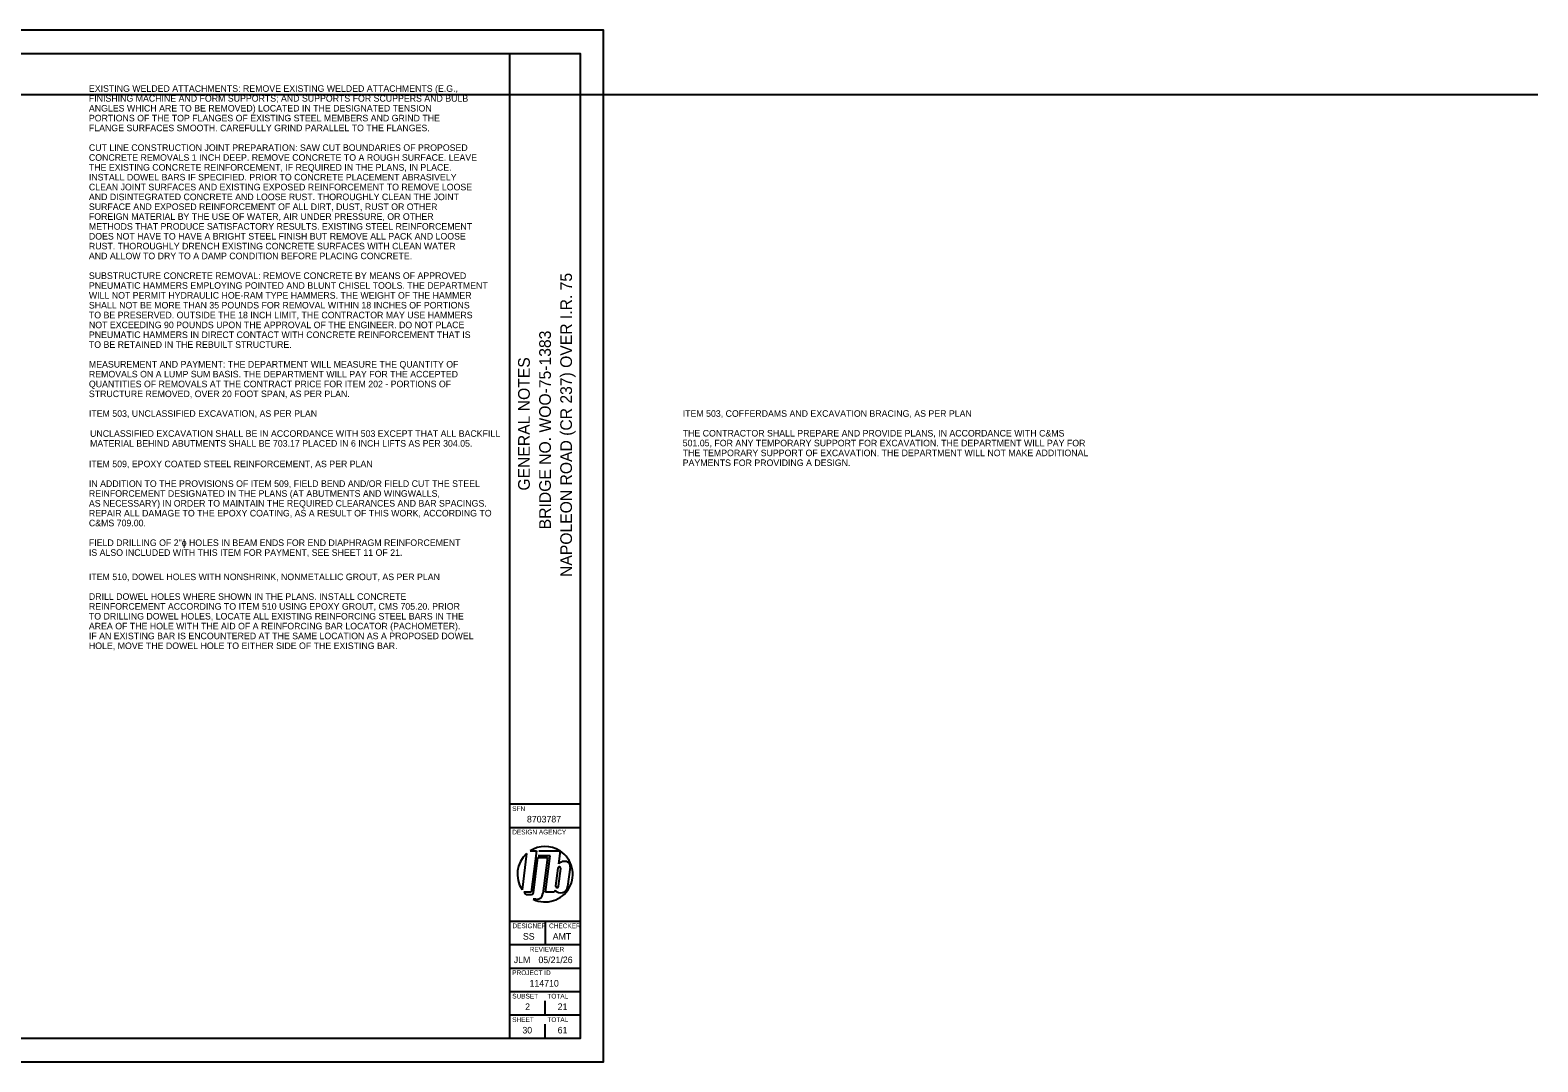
# Model space of a CAD drawing. Extents: x -11.1 to 53.9, y -2 to 22.
# Drawn here: x 21.76 to 53.93, y 0 to 22 of the extents above; entities that cross this region are included whole.
import ezdxf

# ---------------------------------------------------------------- set-up
doc = ezdxf.new("R2010")
doc.units = 0
for name, color, linetype in [('BR_P_Gen_Text', 7, 'Continuous'), ('SC_Scratch1', 7, 'Continuous'), ('SH_Border', 7, 'Continuous'), ('SH_Cut_Line', 7, 'Continuous'), ('SH_Data', 7, 'Continuous')]:
    doc.layers.add(name, color=color, linetype=linetype)

msp = doc.modelspace()

# ---------------------------------------------------------------- linework, layer by layer
at = {"layer": 'SC_Scratch1'}
msp.add_line((2.753, 20.628), (53.932, 20.628), dxfattribs=at)
at = {"layer": 'SH_Border'}
for p, q in [((32, 0.5), (32, 21.5)), ((32, 5.5), (33.5, 5.5)), ((32, 5), (33.5, 5)), ((32, 3), (33.5, 3)), ((32.75, 3), (32.75, 2.5)), ((32, 2.5), (33.5, 2.5)), ((32, 2), (33.5, 2)), ((32, 1.5), (33.5, 1.5)), ((32, 1), (33.5, 1))]:
    msp.add_line(p, q, dxfattribs=at)
msp.add_lwpolyline([(1.5, 21.5), (33.5, 21.5), (33.5, 0.5), (1.5, 0.5)], close=True, dxfattribs=at)
at = {"layer": 'SH_Cut_Line'}
msp.add_lwpolyline([(0, 0), (34, 0), (34, 22), (0, 22)], close=True, dxfattribs=at)
at = {"layer": 'SH_Data'}
for p, q in [((32.356, 4.44), (32.259, 3.671)), ((32.432, 4.498), (32.567, 4.498)), ((32.567, 4.498), (32.456, 3.618)), ((32.504, 3.604), (32.599, 4.355)), ((32.599, 4.355), (32.801, 4.355)), ((32.856, 4.396), (32.604, 4.396)), ((32.617, 4.5), (33.065, 4.5)), ((32.801, 4.355), (32.704, 3.589)), ((32.758, 3.618), (32.856, 4.396)), ((33.07, 4.496), (33.035, 4.22)), ((32.75, 4), (32.75, 4)), ((33.024, 4.131), (32.976, 3.75)), ((33.036, 3.743), (33.084, 4.124)), ((33.283, 4.148), (33.231, 3.737)), ((32.456, 3.618), (32.299, 3.618)), ((32.347, 3.568), (32.462, 3.568)), ((32.947, 3.618), (32.758, 3.618)), ((32.964, 3.661), (32.947, 3.618)), ((32.564, 3.466), (32.498, 3.466)), ((32.75, 1), (32.75, 1.3)), ((32.375, 0.675), (32.375, 0.675)), ((32.75, 0.5), (32.75, 0.8))]:
    msp.add_line(p, q, dxfattribs=at)
for centre, radius, start, end in [((32.75, 4), 0.591, 57.726, 122.5688), ((32.75, 4), 0.591, 131.8253, 213.7822), ((32.75, 4), 0.591, 244.7646, 57.1575), ((33.17, 4.086), 0.19, 105.9444, 135.0487), ((33.164, 4.1), 0.175, 66.6782, 105.4185), ((33.177, 4.169), 0.108, 349.2072, 58.7163), ((33.054, 4.128), 0.0301, 352.3298, 173.2777), ((32.75, 4), 0.591, 220.2786, 227.0158), ((32.462, 3.609), 0.0417, 270, 352.8038), ((32.564, 3.606), 0.141, 270, 352.8038), ((33.081, 3.755), 0.151, 218.6264, 353.0883), ((33.006, 3.746), 0.0301, 172.3335, 353.274)]:
    msp.add_arc(centre, radius, start, end, dxfattribs=at)

# ---------------------------------------------------------------- texts
at = {"layer": 'BR_P_Gen_Text'}
for s, p in [('EXISTING WELDED ATTACHMENTS: REMOVE EXISTING WELDED ATTACHMENTS (E.G.,', (23.018, 20.685)), ('FINISHING MACHINE AND FORM SUPPORTS; AND SUPPORTS FOR SCUPPERS AND BULB', (23.018, 20.475)), ('ANGLES WHICH ARE TO BE REMOVED) LOCATED IN THE DESIGNATED TENSION ', (23.018, 20.265)), ('PORTIONS OF THE TOP FLANGES OF EXISTING STEEL MEMBERS AND GRIND THE ', (23.018, 20.055)), ('FLANGE SURFACES SMOOTH. CAREFULLY GRIND PARALLEL TO THE FLANGES.', (23.018, 19.845)), ('CUT LINE CONSTRUCTION JOINT PREPARATION: SAW CUT BOUNDARIES OF PROPOSED ', (23.018, 19.425)), ('CONCRETE REMOVALS 1 INCH DEEP. REMOVE CONCRETE TO A ROUGH SURFACE. LEAVE ', (23.018, 19.215)), ('THE EXISTING CONCRETE REINFORCEMENT, IF REQUIRED IN THE PLANS, IN PLACE. ', (23.018, 19.005)), ('CLEAN JOINT SURFACES AND EXISTING EXPOSED REINFORCEMENT TO REMOVE LOOSE ', (23.018, 18.585)), ('INSTALL DOWEL BARS IF SPECIFIED. PRIOR TO CONCRETE PLACEMENT ABRASIVELY ', (23.018, 18.795)), ('AND DISINTEGRATED CONCRETE AND LOOSE RUST. THOROUGHLY CLEAN THE JOINT ', (23.018, 18.375)), ('SURFACE AND EXPOSED REINFORCEMENT OF ALL DIRT, DUST, RUST OR OTHER ', (23.018, 18.165)), ('FOREIGN MATERIAL BY THE USE OF WATER, AIR UNDER PRESSURE, OR OTHER ', (23.018, 17.955)), ('METHODS THAT PRODUCE SATISFACTORY RESULTS. EXISTING STEEL REINFORCEMENT ', (23.018, 17.745)), ('DOES NOT HAVE TO HAVE A BRIGHT STEEL FINISH BUT REMOVE ALL PACK AND LOOSE ', (23.018, 17.535)), ('RUST. THOROUGHLY DRENCH EXISTING CONCRETE SURFACES WITH CLEAN WATER ', (23.018, 17.325)), ('AND ALLOW TO DRY TO A DAMP CONDITION BEFORE PLACING CONCRETE. ', (23.018, 17.115)), ('SUBSTRUCTURE CONCRETE REMOVAL: REMOVE CONCRETE BY MEANS OF APPROVED ', (23.018, 16.695)), ('WILL NOT PERMIT HYDRAULIC HOE-RAM TYPE HAMMERS. THE WEIGHT OF THE HAMMER ', (23.018, 16.275)), ('PNEUMATIC HAMMERS EMPLOYING POINTED AND BLUNT CHISEL TOOLS. THE DEPARTMENT ', (23.018, 16.485)), ('SHALL NOT BE MORE THAN 35 POUNDS FOR REMOVAL WITHIN 18 INCHES OF PORTIONS ', (23.018, 16.065)), ('TO BE PRESERVED. OUTSIDE THE 18 INCH LIMIT, THE CONTRACTOR MAY USE HAMMERS ', (23.018, 15.855)), ('NOT EXCEEDING 90 POUNDS UPON THE APPROVAL OF THE ENGINEER. DO NOT PLACE ', (23.018, 15.645)), ('PNEUMATIC HAMMERS IN DIRECT CONTACT WITH CONCRETE REINFORCEMENT THAT IS ', (23.018, 15.435)), ('TO BE RETAINED IN THE REBUILT STRUCTURE. ', (23.018, 15.225)), ('MEASUREMENT AND PAYMENT: THE DEPARTMENT WILL MEASURE THE QUANTITY OF ', (23.018, 14.805)), ('QUANTITIES OF REMOVALS AT THE CONTRACT PRICE FOR ITEM 202 - PORTIONS OF ', (23.018, 14.385)), ('REMOVALS ON A LUMP SUM BASIS. THE DEPARTMENT WILL PAY FOR THE ACCEPTED ', (23.018, 14.595)), ('STRUCTURE REMOVED, OVER 20 FOOT SPAN, AS PER PLAN.', (23.018, 14.175)), ('ITEM 503, UNCLASSIFIED EXCAVATION, AS PER PLAN', (23.018, 13.755)), ('ITEM 503, COFFERDAMS AND EXCAVATION BRACING, AS PER PLAN', (35.687, 13.755)), ('UNCLASSIFIED EXCAVATION SHALL BE IN ACCORDANCE WITH 503 EXCEPT THAT ALL BACKFILL ', (23.043, 13.328)), ('MATERIAL BEHIND ABUTMENTS SHALL BE 703.17 PLACED IN 6 INCH LIFTS AS PER 304.05.', (23.043, 13.118)), ('THE CONTRACTOR SHALL PREPARE AND PROVIDE PLANS, IN ACCORDANCE WITH C&MS ', (35.687, 13.335)), ('501.05, FOR ANY TEMPORARY SUPPORT FOR EXCAVATION. THE DEPARTMENT WILL PAY FOR ', (35.687, 13.125)), ('THE TEMPORARY SUPPORT OF EXCAVATION. THE DEPARTMENT WILL NOT MAKE ADDITIONAL ', (35.687, 12.915)), ('ITEM 509, EPOXY COATED STEEL REINFORCEMENT, AS PER PLAN', (23.018, 12.68)), ('PAYMENTS FOR PROVIDING A DESIGN.', (35.687, 12.705)), ('IN ADDITION TO THE PROVISIONS OF ITEM 509, FIELD BEND AND/OR FIELD CUT THE STEEL', (23.018, 12.26)), ('AS NECESSARY) IN ORDER TO MAINTAIN THE REQUIRED CLEARANCES AND BAR SPACINGS. ', (23.018, 11.84)), ('REINFORCEMENT DESIGNATED IN THE PLANS (AT ABUTMENTS AND WINGWALLS, ', (23.018, 12.05)), ('REPAIR ALL DAMAGE TO THE EPOXY COATING, AS A RESULT OF THIS WORK, ACCORDING TO ', (23.018, 11.63)), ('C&MS 709.00.', (23.018, 11.42)), ('FIELD DRILLING OF 2"ɸ HOLES IN BEAM ENDS FOR END DIAPHRAGM REINFORCEMENT', (23.018, 11)), ('IS ALSO INCLUDED WITH THIS ITEM FOR PAYMENT, SEE SHEET 11 OF 21.', (23.018, 10.79)), ('ITEM 510, DOWEL HOLES WITH NONSHRINK, NONMETALLIC GROUT, AS PER PLAN', (23.018, 10.272)), ('DRILL DOWEL HOLES WHERE SHOWN IN THE PLANS. INSTALL CONCRETE ', (23.018, 9.852)), ('REINFORCEMENT ACCORDING TO ITEM 510 USING EPOXY GROUT, CMS 705.20. PRIOR ', (23.018, 9.642)), ('AREA OF THE HOLE WITH THE AID OF A REINFORCING BAR LOCATOR (PACHOMETER). ', (23.018, 9.222)), ('TO DRILLING DOWEL HOLES, LOCATE ALL EXISTING REINFORCING STEEL BARS IN THE ', (23.018, 9.432)), ('IF AN EXISTING BAR IS ENCOUNTERED AT THE SAME LOCATION AS A PROPOSED DOWEL ', (23.018, 9.012)), ('HOLE, MOVE THE DOWEL HOLE TO EITHER SIDE OF THE EXISTING BAR.', (23.018, 8.802))]:
    msp.add_text(s, height=0.14, dxfattribs=at).set_placement(p)
at = {"layer": 'SH_Data'}
for s, p in [('NAPOLEON ROAD (CR 237) OVER I.R. 75', (33.325, 10.34)), ('BRIDGE NO. WOO-75-1383', (32.875, 11.357)), ('GENERAL NOTES', (32.425, 12.182))]:
    msp.add_text(s, height=0.25, rotation=90, dxfattribs=at).set_placement(p)
for s, height, p in [('SFN', 0.1, (32.05, 5.35)), ('8703787', 0.14, (32.364, 5.105)), ('DESIGN AGENCY', 0.1, (32.05, 4.85)), ('DESIGNER', 0.1, (32.054, 2.85)), ('CHECKER', 0.1, (32.835, 2.85)), ('SS', 0.14, (32.278, 2.605)), ('AMT', 0.14, (32.914, 2.605)), ('REVIEWER', 0.1, (32.422, 2.35)), ('05/21/26', 0.14, (32.609, 2.105)), ('PROJECT ID', 0.1, (32.05, 1.85)), ('JLM', 0.14, (32.083, 2.105)), ('114710', 0.14, (32.419, 1.605)), ('SUBSET', 0.1, (32.05, 1.35)), ('TOTAL', 0.1, (32.8, 1.35)), ('2', 0.14, (32.325, 1.105)), ('21', 0.14, (33.019, 1.105)), ('SHEET', 0.1, (32.05, 0.85)), ('30', 0.14, (32.267, 0.605)), ('TOTAL', 0.1, (32.8, 0.85)), ('61', 0.14, (33.019, 0.605))]:
    msp.add_text(s, height=height, dxfattribs=at).set_placement(p)

doc.saveas('drawing.dxf')
